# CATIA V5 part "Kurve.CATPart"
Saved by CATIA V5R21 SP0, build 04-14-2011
Part number: Kurve
Bounding box of the stored display mesh (mm): x 402.475 to 1979.406, y -108.704 to 310.223, z 618.735 to 1673.906
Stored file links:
  C:\Users\Home\Desktop\Rollkurve_4\Kurve.CATPart

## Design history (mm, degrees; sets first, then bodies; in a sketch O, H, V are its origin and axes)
Set1 "Ableitungen"
  DatumCurve1 "Verbindung.1"
  DatumCurve2 "Verbindung.2"
Body1 (main body)
  CurveSmooth1: CurveToSmooth DatumCurve1
  CurveSmooth2: CurveToSmooth DatumCurve2
  Sweep1: type Segment, GuideCrv (CurveSmooth1; CurveSmooth2), Length1 0, Length2 0
  Sweep2: type Segment, GuideCrv CurveSmooth1, GuideSurf Sweep1, Length1 50, Length2 -5, Angle 90
  Point1: (0, 0, 0), relative to vertex [face of Sweep2 | face of Sweep2]
  Plane1: type Normal, Curve edge [face of Sweep2 | face of Sweep2], RefPoint Point1
  Plane2: type Tangent, Support Sweep2, RefPoint Point1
